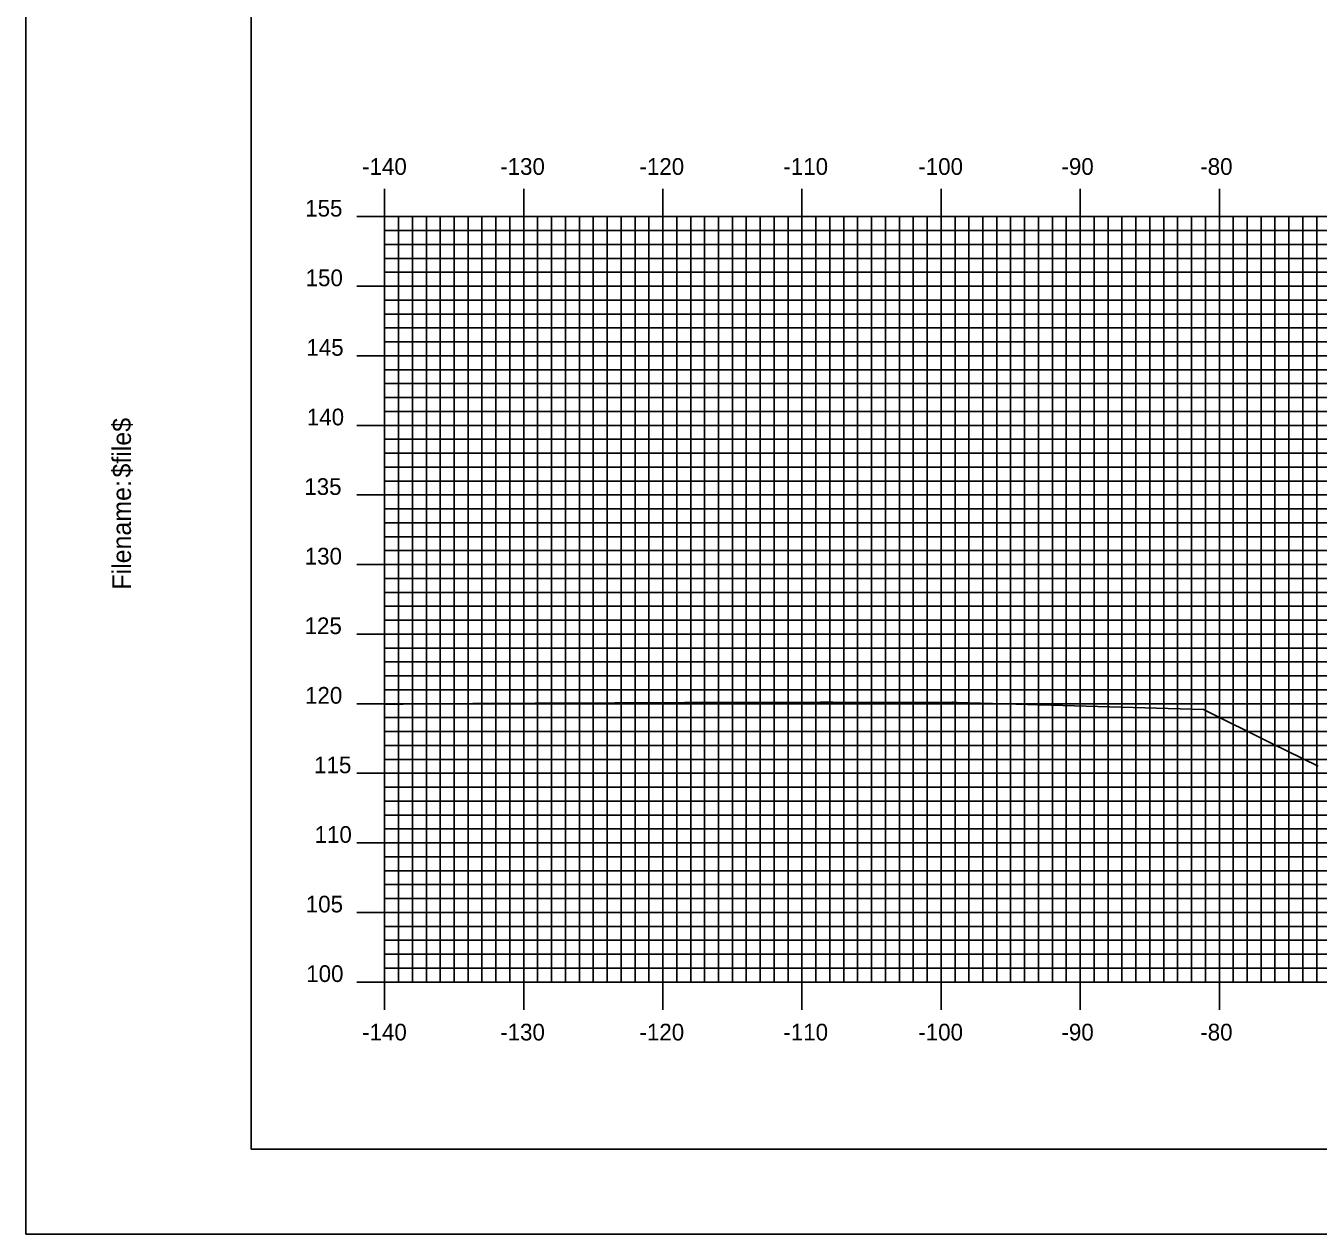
# Model space of a CAD drawing. Extents: x 1685192 to 1685536, y 461260 to 461480.
# Drawn here: x 1685192.4 to 1685285.3, y 461260 to 461346.8 of the extents above; entities that cross this region are included whole.
import ezdxf

# ---------------------------------------------------------------- set-up
doc = ezdxf.new("R2010")
doc.units = 0
for name, color, linetype in [('BORDER', 7, 'Continuous'), ('H_V ANNOTATION', 7, 'Continuous'), ('MAJOR', 7, 'Continuous'), ('MINOR', 7, 'Continuous'), ('PLOT BOUNDARY', 7, 'Continuous'), ('S_Roadway_Centerline', 7, 'Continuous')]:
    doc.layers.add(name, color=color, linetype=linetype)

msp = doc.modelspace()

# ---------------------------------------------------------------- linework, layer by layer
at = {"layer": 'BORDER'}
msp.add_lwpolyline([(1685208.629, 461266.072), (1685528.629, 461266.072), (1685528.629, 461476.072), (1685208.629, 461476.072)], close=True, dxfattribs=at)
at = {"layer": 'MAJOR'}
for p, q in [((1685218.229, 461335.076), (1685218.229, 461333.072)), ((1685228.229, 461335.076), (1685228.229, 461333.072)), ((1685238.229, 461335.076), (1685238.229, 461333.072)), ((1685248.229, 461335.076), (1685248.229, 461333.072)), ((1685258.229, 461335.076), (1685258.229, 461333.072)), ((1685268.229, 461335.076), (1685268.229, 461333.072)), ((1685278.229, 461335.076), (1685278.229, 461333.072)), ((1685216.225, 461333.072), (1685218.229, 461333.072)), ((1685218.229, 461333.072), (1685498.229, 461333.072)), ((1685218.229, 461278.072), (1685218.229, 461333.072)), ((1685218.229, 461278.072), (1685218.229, 461333.072)), ((1685218.229, 461333.072), (1685498.229, 461333.072)), ((1685228.229, 461278.072), (1685228.229, 461333.072)), ((1685238.229, 461278.072), (1685238.229, 461333.072)), ((1685248.229, 461278.072), (1685248.229, 461333.072)), ((1685258.229, 461278.072), (1685258.229, 461333.072)), ((1685268.229, 461278.072), (1685268.229, 461333.072)), ((1685278.229, 461278.072), (1685278.229, 461333.072)), ((1685216.225, 461328.072), (1685218.229, 461328.072)), ((1685218.229, 461328.072), (1685498.229, 461328.072)), ((1685216.225, 461323.072), (1685218.229, 461323.072)), ((1685218.229, 461323.072), (1685498.229, 461323.072)), ((1685216.225, 461318.072), (1685218.229, 461318.072)), ((1685218.229, 461318.072), (1685498.229, 461318.072)), ((1685216.225, 461313.072), (1685218.229, 461313.072)), ((1685218.229, 461313.072), (1685498.229, 461313.072)), ((1685216.225, 461308.072), (1685218.229, 461308.072)), ((1685218.229, 461308.072), (1685498.229, 461308.072)), ((1685216.225, 461303.072), (1685218.229, 461303.072)), ((1685218.229, 461303.072), (1685498.229, 461303.072)), ((1685216.225, 461298.072), (1685218.229, 461298.072)), ((1685218.229, 461298.072), (1685498.229, 461298.072)), ((1685216.225, 461293.072), (1685218.229, 461293.072)), ((1685218.229, 461293.072), (1685498.229, 461293.072)), ((1685216.225, 461288.072), (1685218.229, 461288.072)), ((1685218.229, 461288.072), (1685498.229, 461288.072)), ((1685216.225, 461283.072), (1685218.229, 461283.072)), ((1685218.229, 461283.072), (1685498.229, 461283.072)), ((1685216.225, 461278.072), (1685218.229, 461278.072)), ((1685218.229, 461278.072), (1685498.229, 461278.072)), ((1685218.229, 461278.072), (1685498.229, 461278.072)), ((1685218.229, 461276.068), (1685218.229, 461278.072)), ((1685228.229, 461276.068), (1685228.229, 461278.072)), ((1685238.229, 461276.068), (1685238.229, 461278.072)), ((1685248.229, 461276.068), (1685248.229, 461278.072)), ((1685258.229, 461276.068), (1685258.229, 461278.072)), ((1685268.229, 461276.068), (1685268.229, 461278.072)), ((1685278.229, 461276.068), (1685278.229, 461278.072))]:
    msp.add_line(p, q, dxfattribs=at)
at = {"layer": 'MINOR'}
for p, q in [((1685219.229, 461278.072), (1685219.229, 461333.072)), ((1685220.229, 461278.072), (1685220.229, 461333.072)), ((1685221.229, 461278.072), (1685221.229, 461333.072)), ((1685222.229, 461278.072), (1685222.229, 461333.072)), ((1685223.229, 461278.072), (1685223.229, 461333.072)), ((1685224.229, 461278.072), (1685224.229, 461333.072)), ((1685225.229, 461278.072), (1685225.229, 461333.072)), ((1685226.229, 461278.072), (1685226.229, 461333.072)), ((1685227.229, 461278.072), (1685227.229, 461333.072)), ((1685229.229, 461278.072), (1685229.229, 461333.072)), ((1685230.229, 461278.072), (1685230.229, 461333.072)), ((1685231.229, 461278.072), (1685231.229, 461333.072)), ((1685232.229, 461278.072), (1685232.229, 461333.072)), ((1685233.229, 461278.072), (1685233.229, 461333.072)), ((1685234.229, 461278.072), (1685234.229, 461333.072)), ((1685235.229, 461278.072), (1685235.229, 461333.072)), ((1685236.229, 461278.072), (1685236.229, 461333.072)), ((1685237.229, 461278.072), (1685237.229, 461333.072)), ((1685239.229, 461278.072), (1685239.229, 461333.072)), ((1685240.229, 461278.072), (1685240.229, 461333.072)), ((1685241.229, 461278.072), (1685241.229, 461333.072)), ((1685242.229, 461278.072), (1685242.229, 461333.072)), ((1685243.229, 461278.072), (1685243.229, 461333.072)), ((1685244.229, 461278.072), (1685244.229, 461333.072)), ((1685245.229, 461278.072), (1685245.229, 461333.072)), ((1685246.229, 461278.072), (1685246.229, 461333.072)), ((1685247.229, 461278.072), (1685247.229, 461333.072)), ((1685249.229, 461278.072), (1685249.229, 461333.072)), ((1685250.229, 461278.072), (1685250.229, 461333.072)), ((1685251.229, 461278.072), (1685251.229, 461333.072)), ((1685252.229, 461278.072), (1685252.229, 461333.072)), ((1685253.229, 461278.072), (1685253.229, 461333.072)), ((1685254.229, 461278.072), (1685254.229, 461333.072)), ((1685255.229, 461278.072), (1685255.229, 461333.072)), ((1685256.229, 461278.072), (1685256.229, 461333.072)), ((1685257.229, 461278.072), (1685257.229, 461333.072)), ((1685259.229, 461278.072), (1685259.229, 461333.072)), ((1685260.229, 461278.072), (1685260.229, 461333.072)), ((1685261.229, 461278.072), (1685261.229, 461333.072)), ((1685262.229, 461278.072), (1685262.229, 461333.072)), ((1685263.229, 461278.072), (1685263.229, 461333.072)), ((1685264.229, 461278.072), (1685264.229, 461333.072)), ((1685265.229, 461278.072), (1685265.229, 461333.072)), ((1685266.229, 461278.072), (1685266.229, 461333.072)), ((1685267.229, 461278.072), (1685267.229, 461333.072)), ((1685269.229, 461278.072), (1685269.229, 461333.072)), ((1685270.229, 461278.072), (1685270.229, 461333.072)), ((1685271.229, 461278.072), (1685271.229, 461333.072)), ((1685272.229, 461278.072), (1685272.229, 461333.072)), ((1685273.229, 461278.072), (1685273.229, 461333.072)), ((1685274.229, 461278.072), (1685274.229, 461333.072)), ((1685275.229, 461278.072), (1685275.229, 461333.072)), ((1685276.229, 461278.072), (1685276.229, 461333.072)), ((1685277.229, 461278.072), (1685277.229, 461333.072)), ((1685279.229, 461278.072), (1685279.229, 461333.072)), ((1685280.229, 461278.072), (1685280.229, 461333.072)), ((1685281.229, 461278.072), (1685281.229, 461333.072)), ((1685282.229, 461278.072), (1685282.229, 461333.072)), ((1685283.229, 461278.072), (1685283.229, 461333.072)), ((1685284.229, 461278.072), (1685284.229, 461333.072)), ((1685285.229, 461278.072), (1685285.229, 461333.072)), ((1685218.229, 461332.072), (1685498.229, 461332.072)), ((1685218.229, 461332.072), (1685220.233, 461332.072)), ((1685218.229, 461331.072), (1685498.229, 461331.072)), ((1685218.229, 461331.072), (1685220.233, 461331.072)), ((1685218.229, 461330.072), (1685498.229, 461330.072)), ((1685218.229, 461330.072), (1685220.233, 461330.072)), ((1685218.229, 461329.072), (1685498.229, 461329.072)), ((1685218.229, 461329.072), (1685220.233, 461329.072)), ((1685218.229, 461327.072), (1685498.229, 461327.072)), ((1685218.229, 461327.072), (1685220.233, 461327.072)), ((1685218.229, 461326.072), (1685498.229, 461326.072)), ((1685218.229, 461326.072), (1685220.233, 461326.072)), ((1685218.229, 461325.072), (1685498.229, 461325.072)), ((1685218.229, 461325.072), (1685220.233, 461325.072)), ((1685218.229, 461324.072), (1685498.229, 461324.072)), ((1685218.229, 461324.072), (1685220.233, 461324.072)), ((1685218.229, 461322.072), (1685498.229, 461322.072)), ((1685218.229, 461322.072), (1685220.233, 461322.072)), ((1685218.229, 461321.072), (1685498.229, 461321.072)), ((1685218.229, 461321.072), (1685220.233, 461321.072)), ((1685218.229, 461320.072), (1685498.229, 461320.072)), ((1685218.229, 461320.072), (1685220.233, 461320.072)), ((1685218.229, 461319.072), (1685498.229, 461319.072)), ((1685218.229, 461319.072), (1685220.233, 461319.072)), ((1685218.229, 461317.072), (1685498.229, 461317.072)), ((1685218.229, 461317.072), (1685220.233, 461317.072)), ((1685218.229, 461316.072), (1685498.229, 461316.072)), ((1685218.229, 461316.072), (1685220.233, 461316.072)), ((1685218.229, 461315.072), (1685498.229, 461315.072)), ((1685218.229, 461315.072), (1685220.233, 461315.072)), ((1685218.229, 461314.072), (1685498.229, 461314.072)), ((1685218.229, 461314.072), (1685220.233, 461314.072)), ((1685218.229, 461312.072), (1685498.229, 461312.072)), ((1685218.229, 461312.072), (1685220.233, 461312.072)), ((1685218.229, 461311.072), (1685498.229, 461311.072)), ((1685218.229, 461311.072), (1685220.233, 461311.072)), ((1685218.229, 461310.072), (1685498.229, 461310.072)), ((1685218.229, 461310.072), (1685220.233, 461310.072)), ((1685218.229, 461309.072), (1685498.229, 461309.072)), ((1685218.229, 461309.072), (1685220.233, 461309.072)), ((1685218.229, 461307.072), (1685498.229, 461307.072)), ((1685218.229, 461307.072), (1685220.233, 461307.072)), ((1685218.229, 461306.072), (1685498.229, 461306.072)), ((1685218.229, 461306.072), (1685220.233, 461306.072)), ((1685218.229, 461305.072), (1685498.229, 461305.072)), ((1685218.229, 461305.072), (1685220.233, 461305.072)), ((1685218.229, 461304.072), (1685498.229, 461304.072)), ((1685218.229, 461304.072), (1685220.233, 461304.072)), ((1685218.229, 461302.072), (1685498.229, 461302.072)), ((1685218.229, 461302.072), (1685220.233, 461302.072)), ((1685218.229, 461301.072), (1685498.229, 461301.072)), ((1685218.229, 461301.072), (1685220.233, 461301.072)), ((1685218.229, 461300.072), (1685498.229, 461300.072)), ((1685218.229, 461300.072), (1685220.233, 461300.072)), ((1685218.229, 461299.072), (1685498.229, 461299.072)), ((1685218.229, 461299.072), (1685220.233, 461299.072)), ((1685218.229, 461297.072), (1685498.229, 461297.072)), ((1685218.229, 461297.072), (1685220.233, 461297.072)), ((1685218.229, 461296.072), (1685498.229, 461296.072)), ((1685218.229, 461296.072), (1685220.233, 461296.072)), ((1685218.229, 461295.072), (1685498.229, 461295.072)), ((1685218.229, 461295.072), (1685220.233, 461295.072)), ((1685218.229, 461294.072), (1685498.229, 461294.072)), ((1685218.229, 461294.072), (1685220.233, 461294.072)), ((1685218.229, 461292.072), (1685498.229, 461292.072)), ((1685218.229, 461292.072), (1685220.233, 461292.072)), ((1685218.229, 461291.072), (1685498.229, 461291.072)), ((1685218.229, 461291.072), (1685220.233, 461291.072)), ((1685218.229, 461290.072), (1685498.229, 461290.072)), ((1685218.229, 461290.072), (1685220.233, 461290.072)), ((1685218.229, 461289.072), (1685498.229, 461289.072)), ((1685218.229, 461289.072), (1685220.233, 461289.072)), ((1685218.229, 461287.072), (1685498.229, 461287.072)), ((1685218.229, 461287.072), (1685220.233, 461287.072)), ((1685218.229, 461286.072), (1685498.229, 461286.072)), ((1685218.229, 461286.072), (1685220.233, 461286.072)), ((1685218.229, 461285.072), (1685498.229, 461285.072)), ((1685218.229, 461285.072), (1685220.233, 461285.072)), ((1685218.229, 461284.072), (1685498.229, 461284.072)), ((1685218.229, 461284.072), (1685220.233, 461284.072)), ((1685218.229, 461282.072), (1685498.229, 461282.072)), ((1685218.229, 461282.072), (1685220.233, 461282.072)), ((1685218.229, 461281.072), (1685498.229, 461281.072)), ((1685218.229, 461281.072), (1685220.233, 461281.072)), ((1685218.229, 461280.072), (1685498.229, 461280.072)), ((1685218.229, 461280.072), (1685220.233, 461280.072)), ((1685218.229, 461279.072), (1685498.229, 461279.072)), ((1685218.229, 461279.072), (1685220.233, 461279.072))]:
    msp.add_line(p, q, dxfattribs=at)
at = {"layer": 'PLOT BOUNDARY'}
msp.add_lwpolyline([(1685192.443, 461259.954), (1685532.443, 461259.954), (1685532.443, 461479.954), (1685192.443, 461479.954)], close=True, dxfattribs=at)
at = {"layer": 'S_Roadway_Centerline'}
for points in [[(1685218.229, 461298.029), (1685219.557, 461298.048), (1685220.725, 461298.071), (1685224.578, 461298.086), (1685224.839, 461298.078), (1685229.063, 461298.097), (1685229.306, 461298.098), (1685229.902, 461298.101), (1685230.121, 461298.103), (1685230.428, 461298.112), (1685234.785, 461298.129), (1685235.127, 461298.134), (1685239.807, 461298.15), (1685240.046, 461298.148), (1685240.137, 461298.149), (1685240.19, 461298.15), (1685244.456, 461298.159), (1685244.595, 461298.155), (1685249.555, 461298.169), (1685249.571, 461298.169), (1685249.579, 461298.17), (1685250.438, 461298.172), (1685254.526, 461298.159), (1685254.656, 461298.159), (1685259.03, 461298.17), (1685259.047, 461298.17), (1685259.073, 461298.17), (1685259.102, 461298.169), (1685259.266, 461298.166), (1685259.392, 461298.162), (1685277.082, 461297.664)], [(1685277.082, 461297.665), (1685281.952, 461295.238), (1685285.33, 461293.588)]]:
    msp.add_lwpolyline(points, dxfattribs=at)

# ---------------------------------------------------------------- texts
at = {"layer": 'BORDER'}
for s, p in [('$file$', (1685199.999, 461314.323)), ('Filename:', (1685199.999, 461306.269))]:
    msp.add_text(s, height=1.3392, rotation=90, dxfattribs=at).set_placement(p)
at = {"layer": 'H_V ANNOTATION'}
for s, p in [('-140', (1685216.613, 461336.072)), ('-130', (1685226.538, 461336.072)), ('-120', (1685236.549, 461336.072)), ('-110', (1685246.892, 461336.072)), ('-100', (1685256.592, 461336.072)), ('-90', (1685266.881, 461336.072)), ('-80', (1685276.859, 461336.072)), ('155', (1685212.521, 461333.072)), ('150', (1685212.553, 461328.072)), ('145', (1685212.607, 461323.072)), ('140', (1685212.639, 461318.072)), ('135', (1685212.457, 461313.072)), ('130', (1685212.489, 461308.072)), ('125', (1685212.478, 461303.072)), ('120', (1685212.51, 461298.072)), ('115', (1685213.164, 461293.072)), ('110', (1685213.196, 461288.072)), ('105', (1685212.564, 461283.072)), ('100', (1685212.596, 461278.072)), ('-140', (1685216.613, 461273.872)), ('-130', (1685226.538, 461273.872)), ('-120', (1685236.549, 461273.872)), ('-110', (1685246.892, 461273.872)), ('-100', (1685256.592, 461273.872)), ('-90', (1685266.881, 461273.872)), ('-80', (1685276.859, 461273.872))]:
    msp.add_text(s, height=1.2, dxfattribs=at).set_placement(p)
at = {"layer": 'MAJOR'}
msp.add_text('-', height=0.012, dxfattribs=at).set_placement((1685218.22, 461278.072))

doc.saveas('drawing.dxf')
